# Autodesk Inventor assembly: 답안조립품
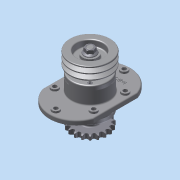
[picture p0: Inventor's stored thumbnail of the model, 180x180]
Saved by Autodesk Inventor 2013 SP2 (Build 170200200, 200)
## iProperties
Created: 2015-02
Part Number: 답안조립품
Document SubType Name: Assembly
Designer: dgall
Author: dgall
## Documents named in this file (12)
- C:\Documents and Settings\dgall\바탕 화면\450207V1029\답안조립품.iam
- C:\Documents and Settings\dgall\바탕 화면\450207V1029\1-본체.ipt
- C:\Documents and Settings\dgall\바탕 화면\450207V1029\2-커버.ipt
- C:\Documents and Settings\dgall\바탕 화면\450207V1029\8-오일실 30x42.ipt
- C:\Documents and Settings\dgall\바탕 화면\450207V1029\6-베어링 6206.ipt
- C:\Documents and Settings\dgall\바탕 화면\450207V1029\7-부시.ipt
- C:\Documents and Settings\dgall\바탕 화면\450207V1029\11-키 6x6.ipt
- C:\Documents and Settings\dgall\바탕 화면\450207V1029\9-M16-너트.ipt
- C:\Documents and Settings\dgall\바탕 화면\450207V1029\3-축.ipt
- C:\Documents and Settings\dgall\바탕 화면\450207V1029\10-M6.ipt
- C:\Documents and Settings\dgall\바탕 화면\450207V1029\4-V벨트풀리.ipt
- C:\Documents and Settings\dgall\바탕 화면\450207V1029\5-체인 스프로킷.ipt
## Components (23 placed, 11 different names)
1. 1-본체:1
2. 2-커버:1
3. 2-커버:2
4. 8-8-오일실 30x42:1
5. 6-베어링 6206:1
6. 7-부시:1
7. 6-베어링 6206:2
8. 8-8-오일실 30x42:2
9. 11-키 6x6:1
10. 9-M16 너트:1
11. 3-축:1
12. 11-키 6x6:2
13. 4-V벨트풀리:1
14. 9-M16 너트:2
15. 5-체인 스프로킷:1
16. 10-M6:2
17. 10-M6:3
18. 10-M6:4
19. 10-M6:5
20. 10-M6:1
21. 10-M6:6
22. 10-M6:7
23. 10-M6:8
